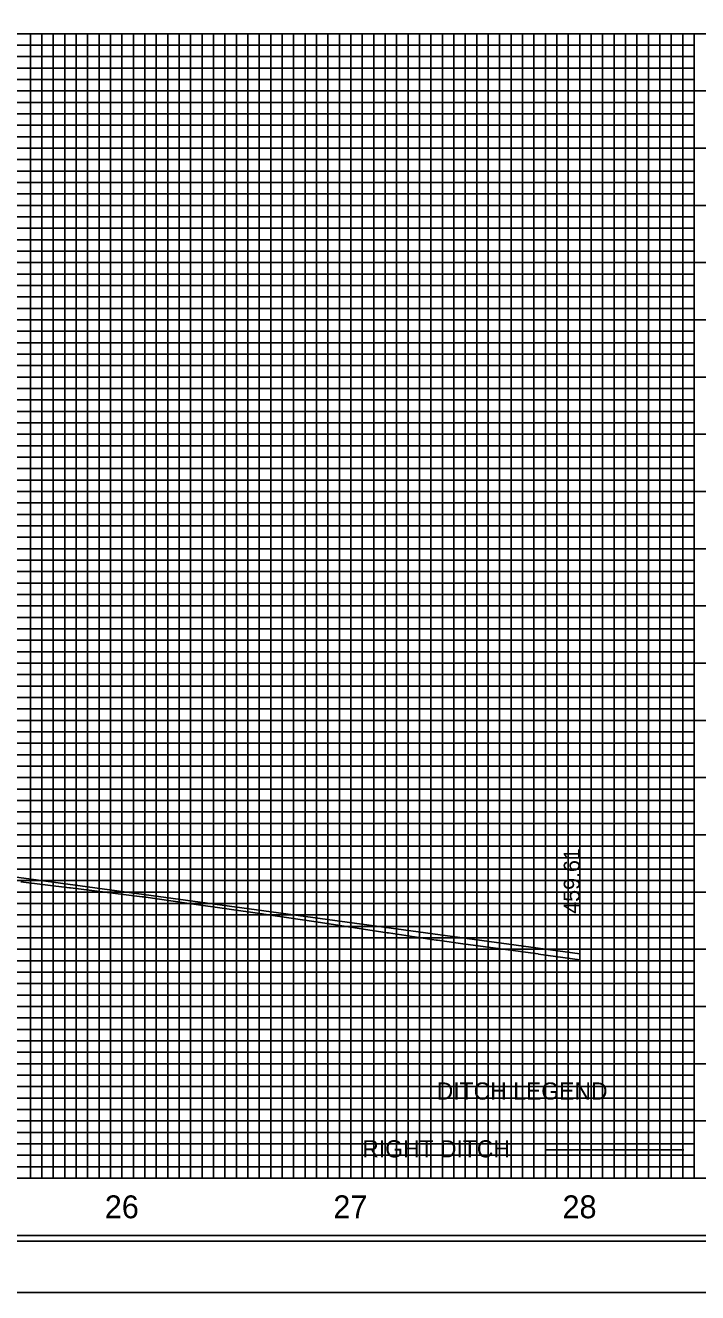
# Model space of a CAD drawing. Extents: x 571503 to 593215, y -77195 to -51828.
# Drawn here: x 583655 to 583949, y -72483 to -71929 of the extents above; entities that cross this region are included whole.
import ezdxf

# ---------------------------------------------------------------- set-up
doc = ezdxf.new("R2010")
doc.units = 0
for name, color, linetype in [('Exist Vertical Profile Ground Line', 7, 'Continuous'), ('Exist Vertical Profile Horizontal Axis Label Major', 7, 'Continuous'), ('Prop Grid Mask', 7, 'Continuous'), ('Prop PFL Ditch Label CELL', 7, 'Continuous'), ('Prop Vertical Profile Grade', 7, 'Continuous'), ('Prop VPI Label', 7, 'Continuous'), ('Sheet Cutting Line CELL', 7, 'Continuous'), ('Sheet DOT Grid CELL', 7, 'Continuous'), ('Sheet Layout Profile Border Port 2', 7, 'Continuous'), ('Sheet Plot Border Inside CELL', 7, 'Continuous'), ('Sheet Plot Border Outside CELL', 7, 'Continuous'), ('Sheet Profile CELL', 7, 'Continuous'), ('Sheet Profile Grid Major CELL', 7, 'Continuous'), ('Sheet Profile Grid Middle CELL', 7, 'Continuous'), ('Sheet Profile Grid Minor CELL', 7, 'Continuous')]:
    doc.layers.add(name, color=color, linetype=linetype)

msp = doc.modelspace()

# ---------------------------------------------------------------- linework, layer by layer
at = {"layer": 'Exist Vertical Profile Ground Line'}
msp.add_lwpolyline([(583652.76, -72303.32), (583674.03, -72305.96), (583674.42, -72306.01), (583705.78, -72309.9), (583706.39, -72309.97), (583726.33, -72312.8), (583727.38, -72312.95), (583758.27, -72317.34), (583758.89, -72317.43), (583780.78, -72320.75), (583781.77, -72320.91), (583812.9, -72325.64), (583813.36, -72325.71), (583834.24, -72328.8), (583834.84, -72328.9), (583846.99, -72330.55), (583847.09, -72330.57), (583878.84, -72334.88), (583879.03, -72334.91), (583896.98, -72337.47)], dxfattribs=at)
at = {"layer": 'Prop Grid Mask'}
for points in [[(583796.98, -72382.85), (583946.98, -72382.85), (583946.98, -72407.85), (583796.98, -72407.85)], [(583796.98, -72407.85), (583946.98, -72407.85), (583946.98, -72432.85), (583796.98, -72432.85)]]:
    msp.add_lwpolyline(points, close=True, dxfattribs=at)
at = {"layer": 'Prop PFL Ditch Label CELL'}
for p, q in [((583882.53, -72420.5), (583942.53, -72420.5)), ((583796.98, -72422.85), (583796.98, -72422.85))]:
    msp.add_line(p, q, dxfattribs=at)
at = {"layer": 'Prop Vertical Profile Grade'}
msp.add_line((583631.98, -72298.75), (583896.98, -72334.8), dxfattribs=at)
at = {"layer": 'Sheet Cutting Line CELL'}
msp.add_line((582329.98, -72482.85), (584013.98, -72482.85), dxfattribs=at)
at = {"layer": 'Sheet DOT Grid CELL'}
for p, q in [((582496.98, -71932.85), (583996.87, -71932.85)), ((583696.98, -71932.85), (583696.98, -72432.85)), ((583746.98, -71932.85), (583746.98, -72432.85)), ((583796.98, -71932.85), (583796.98, -72432.85)), ((583846.98, -71932.85), (583846.98, -72432.85)), ((583896.98, -71932.85), (583896.98, -72432.85)), ((583946.98, -71932.85), (583946.98, -72432.85)), ((582496.98, -71982.85), (583996.87, -71982.85)), ((582496.98, -72032.85), (583996.87, -72032.85)), ((582496.98, -72082.85), (583996.87, -72082.85)), ((582496.98, -72132.85), (583996.87, -72132.85)), ((582496.98, -72182.85), (583996.87, -72182.85)), ((582496.98, -72232.85), (583996.87, -72232.85)), ((582496.98, -72282.85), (583996.87, -72282.85)), ((582496.98, -72332.85), (583996.87, -72332.85)), ((582496.98, -72382.85), (583996.87, -72382.85))]:
    msp.add_line(p, q, dxfattribs=at)
at = {"layer": 'Sheet Layout Profile Border Port 2'}
msp.add_lwpolyline([(582546.98, -71932.85), (583946.98, -71932.85), (583946.98, -72432.85), (582546.98, -72432.85)], close=True, dxfattribs=at)
at = {"layer": 'Sheet Plot Border Inside CELL'}
msp.add_lwpolyline([(582342.98, -72460.4), (584009.48, -72460.4), (584009.48, -71405.3), (582342.98, -71405.3)], close=True, dxfattribs=at)
at = {"layer": 'Sheet Plot Border Outside CELL'}
msp.add_lwpolyline([(582329.98, -72482.85), (584013.98, -72482.85), (584013.98, -71382.85), (582329.98, -71382.85)], close=True, dxfattribs=at)
at = {"layer": 'Sheet Profile CELL'}
for p, q in [((582496.98, -71932.85), (583996.98, -71932.85)), ((583996.98, -72432.85), (582496.98, -72432.85)), ((582496.98, -72457.85), (583996.98, -72457.85))]:
    msp.add_line(p, q, dxfattribs=at)
msp.add_lwpolyline([(583996.98, -71407.85), (582496.98, -71407.85), (582496.98, -72457.85), (583996.98, -72457.85)], close=True, dxfattribs=at)
at = {"layer": 'Sheet Profile Grid Major CELL'}
for p, q in [((583696.98, -71932.85), (583746.98, -71932.85)), ((583796.98, -71932.85), (583846.98, -71932.85)), ((583896.98, -71932.85), (583946.98, -71932.85)), ((583896.98, -72432.85), (583896.98, -72432.85))]:
    msp.add_line(p, q, dxfattribs=at)
for points in [[(583646.98, -72432.85), (583696.98, -72432.85), (583696.98, -71932.85), (583746.98, -71932.85), (583746.98, -72432.85), (583796.98, -72432.85), (583796.98, -71932.85), (583846.98, -71932.85), (583846.98, -72432.85), (583896.98, -72432.85), (583896.98, -72432.85), (583896.98, -71932.85), (583946.98, -71932.85), (583946.98, -72432.85)], [(583996.98, -71982.85), (582496.98, -71982.85)], [(583996.98, -72032.85), (582496.98, -72032.85), (582496.98, -72082.85), (583996.98, -72082.85)], [(583996.98, -72132.85), (582496.98, -72132.85), (582496.98, -72182.85), (583996.98, -72182.85)], [(583996.98, -72232.85), (582496.98, -72232.85), (582496.98, -72282.85), (583996.98, -72282.85)], [(583996.98, -72332.85), (582496.98, -72332.85), (582496.98, -72332.85), (582496.98, -72382.85), (583996.98, -72382.85)], [(583996.98, -72432.85), (582496.98, -72432.85)]]:
    msp.add_lwpolyline(points, dxfattribs=at)
at = {"layer": 'Sheet Profile Grid Middle CELL'}
for points in [[(583621.98, -71932.85), (583671.98, -71932.85), (583671.98, -72432.85), (583721.98, -72432.85), (583721.98, -71932.85), (583771.98, -71932.85), (583771.98, -72432.85), (583821.98, -72432.85), (583821.98, -71932.85), (583871.98, -71932.85), (583871.98, -72432.85), (583921.98, -72432.85), (583921.98, -71932.85)], [(582496.98, -71957.85), (583996.98, -71957.85)], [(583996.98, -72007.85), (582496.98, -72007.85), (582496.98, -72057.85), (583996.98, -72057.85)], [(583996.98, -72107.85), (582496.98, -72107.85), (582496.98, -72157.85), (583996.98, -72157.85)], [(583996.98, -72207.85), (582496.98, -72207.85), (582496.98, -72257.85), (583996.98, -72257.85)], [(583996.98, -72307.85), (582496.98, -72307.85), (582496.98, -72357.85), (583996.98, -72357.85)], [(583996.98, -72407.85), (582496.98, -72407.85)]]:
    msp.add_lwpolyline(points, dxfattribs=at)
at = {"layer": 'Sheet Profile Grid Minor CELL'}
for p, q in [((582546.98, -71937.85), (583946.98, -71937.85)), ((583946.98, -71942.85), (582546.98, -71942.85)), ((582546.98, -71947.85), (583946.98, -71947.85)), ((583946.98, -71952.85), (582546.98, -71952.85)), ((582546.98, -71962.85), (583946.98, -71962.85)), ((583946.98, -71967.85), (582546.98, -71967.85)), ((582546.98, -71972.85), (583946.98, -71972.85)), ((583946.98, -71977.85), (582546.98, -71977.85)), ((582546.98, -71987.85), (583946.98, -71987.85)), ((583946.98, -71992.85), (582546.98, -71992.85)), ((582546.98, -71997.85), (583946.98, -71997.85)), ((583946.98, -72002.85), (582546.98, -72002.85)), ((582546.98, -72012.85), (583946.98, -72012.85)), ((583946.98, -72017.85), (582546.98, -72017.85)), ((582546.98, -72022.85), (583946.98, -72022.85)), ((583946.98, -72027.85), (582546.98, -72027.85)), ((582546.98, -72037.85), (583946.98, -72037.85)), ((583946.98, -72042.85), (582546.98, -72042.85)), ((582546.98, -72047.85), (583946.98, -72047.85)), ((583946.98, -72052.85), (582546.98, -72052.85)), ((582546.98, -72062.85), (583946.98, -72062.85)), ((583946.98, -72067.85), (582546.98, -72067.85)), ((582546.98, -72072.85), (583946.98, -72072.85)), ((583946.98, -72077.85), (582546.98, -72077.85)), ((582546.98, -72087.85), (583946.98, -72087.85)), ((583946.98, -72092.85), (582546.98, -72092.85)), ((582546.98, -72097.85), (583946.98, -72097.85)), ((583946.98, -72102.85), (582546.98, -72102.85)), ((582546.98, -72112.85), (583946.98, -72112.85)), ((583946.98, -72117.85), (582546.98, -72117.85)), ((582546.98, -72122.85), (583946.98, -72122.85)), ((583946.98, -72127.85), (582546.98, -72127.7)), ((582546.98, -72137.85), (583946.98, -72137.85)), ((583946.98, -72142.85), (582546.98, -72142.85)), ((582546.98, -72147.85), (583946.98, -72147.85)), ((583946.98, -72152.85), (582546.98, -72152.85)), ((582546.98, -72162.85), (583946.98, -72162.85)), ((583946.98, -72167.85), (582546.98, -72167.85)), ((582546.98, -72172.85), (583946.98, -72172.85)), ((583946.98, -72177.85), (582546.98, -72177.85)), ((582546.98, -72187.85), (583946.98, -72187.85)), ((583946.98, -72192.85), (582546.98, -72192.85)), ((582546.98, -72197.85), (583946.98, -72197.85)), ((583946.98, -72202.85), (582546.98, -72202.85)), ((582546.98, -72212.85), (583946.98, -72212.85)), ((583946.98, -72217.85), (582546.98, -72217.85)), ((582546.98, -72222.85), (583946.98, -72222.85)), ((583946.98, -72227.85), (582546.98, -72227.85)), ((582546.98, -72237.85), (583946.98, -72237.85)), ((583946.98, -72242.85), (582546.98, -72242.85)), ((582546.98, -72247.85), (583946.98, -72247.85)), ((583946.98, -72252.85), (582546.98, -72252.85)), ((582546.98, -72262.85), (583946.98, -72262.85)), ((583946.98, -72267.85), (582546.98, -72267.85)), ((582546.98, -72272.85), (583946.98, -72272.85)), ((583946.98, -72277.85), (582546.98, -72277.85)), ((582546.98, -72287.85), (583946.98, -72287.85)), ((583946.98, -72292.85), (582546.98, -72292.85)), ((582546.98, -72297.85), (583946.98, -72297.85)), ((583946.98, -72302.85), (582546.98, -72302.85)), ((582546.98, -72312.85), (583946.98, -72312.85)), ((583946.98, -72317.85), (582546.98, -72317.85)), ((582546.98, -72322.85), (583946.98, -72322.85)), ((583946.98, -72327.85), (582546.98, -72327.85)), ((582546.98, -72337.85), (583946.98, -72337.85)), ((583946.98, -72342.85), (582546.98, -72342.85)), ((582546.98, -72347.85), (583946.98, -72347.85)), ((583946.98, -72352.85), (582546.98, -72352.85)), ((582546.98, -72362.85), (583946.98, -72362.85)), ((583946.98, -72367.85), (582546.98, -72367.85)), ((582546.98, -72372.85), (583946.98, -72372.85)), ((583946.98, -72377.85), (582546.98, -72377.85)), ((582546.98, -72387.85), (583946.98, -72387.85)), ((583946.98, -72392.85), (582546.98, -72392.85)), ((582546.98, -72397.85), (583946.98, -72397.85)), ((583946.98, -72402.85), (582546.98, -72402.85)), ((582546.98, -72412.85), (583946.98, -72412.85)), ((583946.98, -72417.85), (582546.98, -72417.85)), ((582546.98, -72422.85), (583946.98, -72422.85)), ((582546.98, -72427.85), (583946.98, -72427.85)), ((583946.98, -72427.85), (583946.98, -72427.85))]:
    msp.add_line(p, q, dxfattribs=at)
for points in [[(583651.98, -72432.85), (583656.98, -72432.85), (583656.98, -71932.85), (583661.98, -71932.85), (583661.98, -72432.85), (583666.98, -72432.85), (583666.98, -71932.85), (583676.98, -71932.85), (583676.98, -72432.85), (583681.98, -72432.85), (583681.98, -71932.85), (583686.98, -71932.85), (583686.98, -72432.85)], [(583686.98, -72432.85), (583691.98, -72432.85), (583691.98, -71932.85), (583701.98, -71932.85), (583701.98, -72432.85), (583706.98, -72432.85), (583706.98, -71932.85), (583711.98, -71932.85), (583711.98, -72432.85), (583716.98, -72432.85), (583716.98, -71932.85), (583726.98, -71932.85), (583726.98, -72432.85), (583731.98, -72432.85), (583731.98, -71932.85), (583736.98, -71932.85), (583736.98, -72432.85), (583741.98, -72432.85), (583741.98, -71932.85), (583751.98, -71932.85), (583751.98, -72432.85), (583756.98, -72432.85), (583756.98, -71932.85), (583761.98, -71932.85), (583761.98, -72432.85), (583766.98, -72432.85), (583766.98, -71932.85), (583776.98, -71932.85), (583776.98, -72432.85), (583781.98, -72432.85), (583781.98, -71932.85), (583786.98, -71932.85), (583786.98, -72432.85), (583791.98, -72432.85), (583791.98, -71932.85), (583801.98, -71932.85), (583801.98, -72432.85), (583806.98, -72432.85), (583806.98, -71932.85), (583811.98, -71932.85), (583811.98, -72432.85), (583816.98, -72432.85), (583816.98, -71932.85), (583826.98, -71932.85), (583826.98, -72432.85), (583831.98, -72432.85), (583831.98, -71932.85), (583836.98, -71932.85), (583836.98, -72432.85), (583841.98, -72432.85), (583841.98, -71932.85), (583851.98, -71932.85), (583851.98, -72432.85), (583856.98, -72432.85), (583856.98, -71932.85), (583861.98, -71932.85), (583861.98, -72432.85), (583866.98, -72432.85), (583866.98, -71932.85), (583876.98, -71932.85), (583876.98, -72432.85), (583881.98, -72432.85), (583881.98, -71932.85), (583886.98, -71932.85), (583886.98, -72432.85), (583891.98, -72432.85), (583891.98, -71932.85), (583901.98, -71932.85), (583901.98, -72432.85), (583906.98, -72432.85), (583906.98, -71932.85), (583911.98, -71932.85), (583911.98, -72432.85), (583916.98, -72432.85), (583916.98, -71932.85), (583926.98, -71932.85), (583926.98, -72432.85), (583931.98, -72432.85), (583931.98, -71932.85), (583936.98, -71932.85), (583936.98, -72432.85), (583941.98, -72432.85), (583941.98, -71932.85), (583946.98, -71932.85)]]:
    msp.add_lwpolyline(points, dxfattribs=at)

# ---------------------------------------------------------------- texts
at = {"layer": 'Exist Vertical Profile Horizontal Axis Label Major'}
for s, p in [('26', (583689.47, -72450.35)), ('27', (583789.33, -72450.35)), ('28', (583889.45, -72450.35))]:
    msp.add_text(s, height=10, dxfattribs=at).set_placement(p)
at = {"layer": 'Prop PFL Ditch Label CELL'}
for s, height, p in [('DITCH LEGEND', 7.5, (583834.48, -72398.5)), ('RIGHT DITCH', 7.485, (583801.98, -72423.75))]:
    msp.add_text(s, height=height, dxfattribs=at).set_placement(p)
at = {"layer": 'Prop VPI Label'}
msp.add_text('459.61', height=7, rotation=90, dxfattribs=at).set_placement((583896.98, -72317.3))

doc.saveas('drawing.dxf')
